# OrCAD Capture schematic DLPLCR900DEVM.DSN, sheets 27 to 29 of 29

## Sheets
27 P22-Slave Pwr/Gnd: size A3
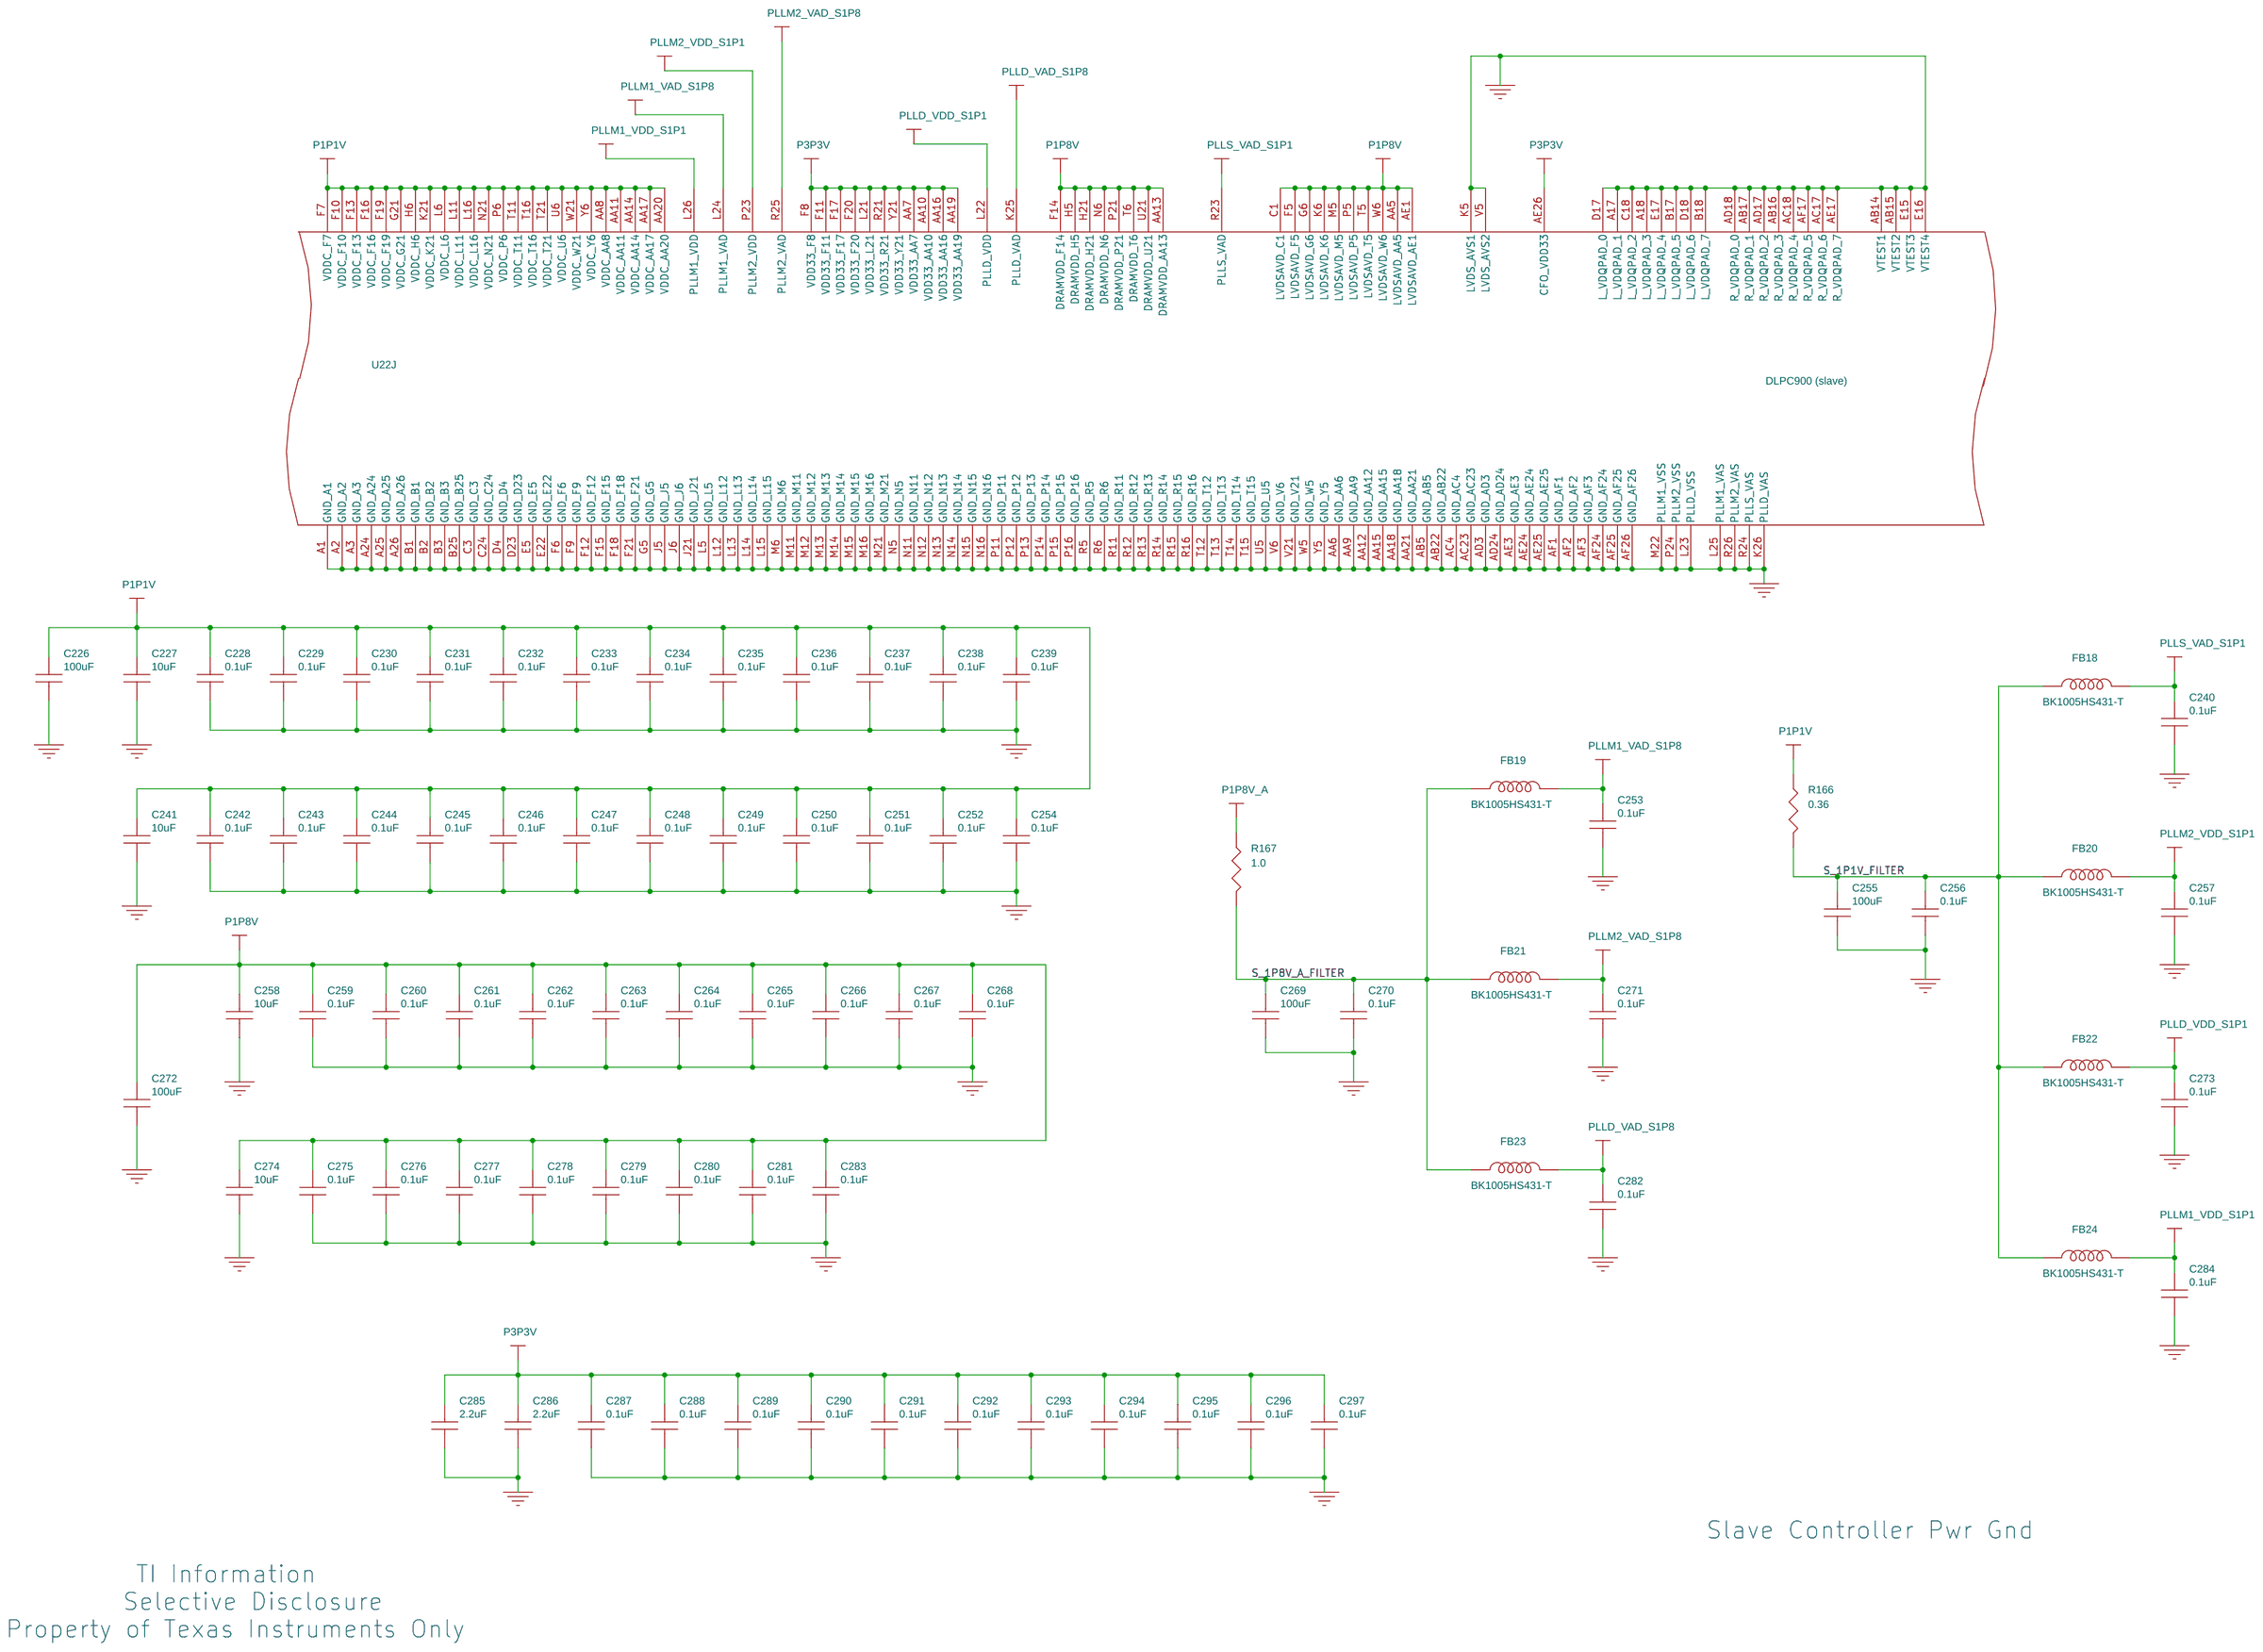
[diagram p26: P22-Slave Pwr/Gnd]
28 P17-Master Pwr/Gnd: size A3
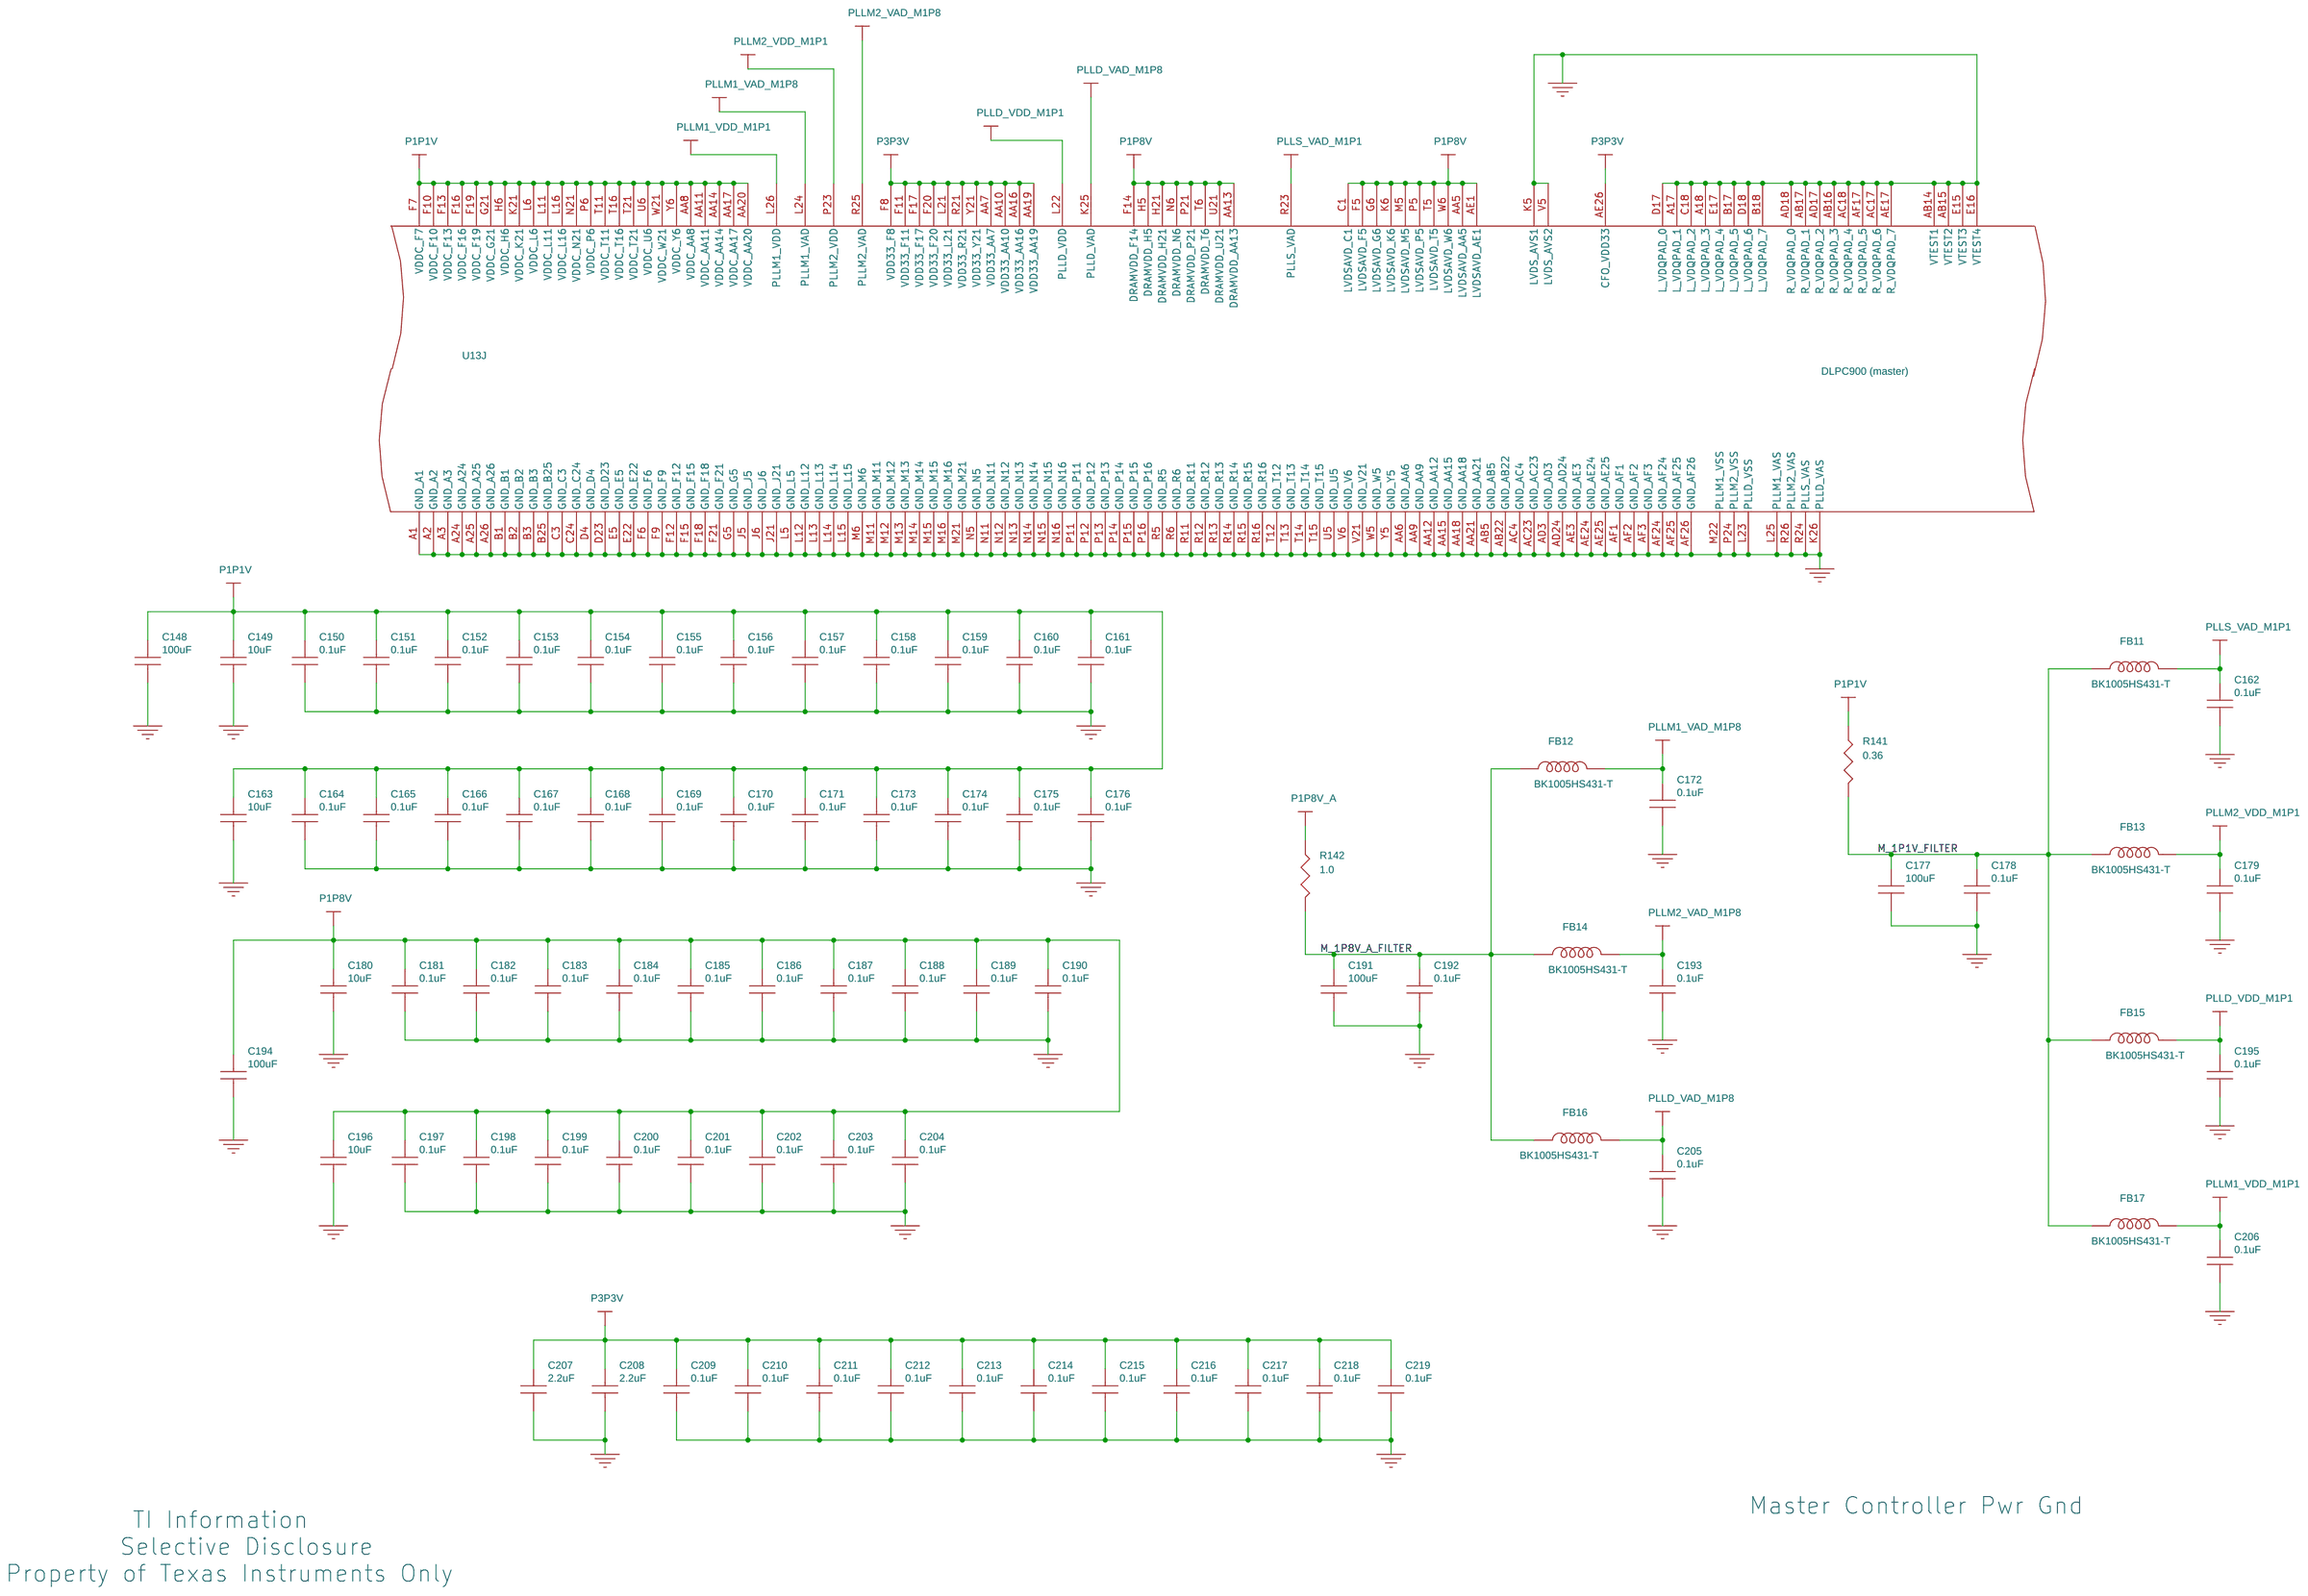
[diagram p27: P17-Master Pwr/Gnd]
29 P05-HDMI/DP Conn, ESD: size A3
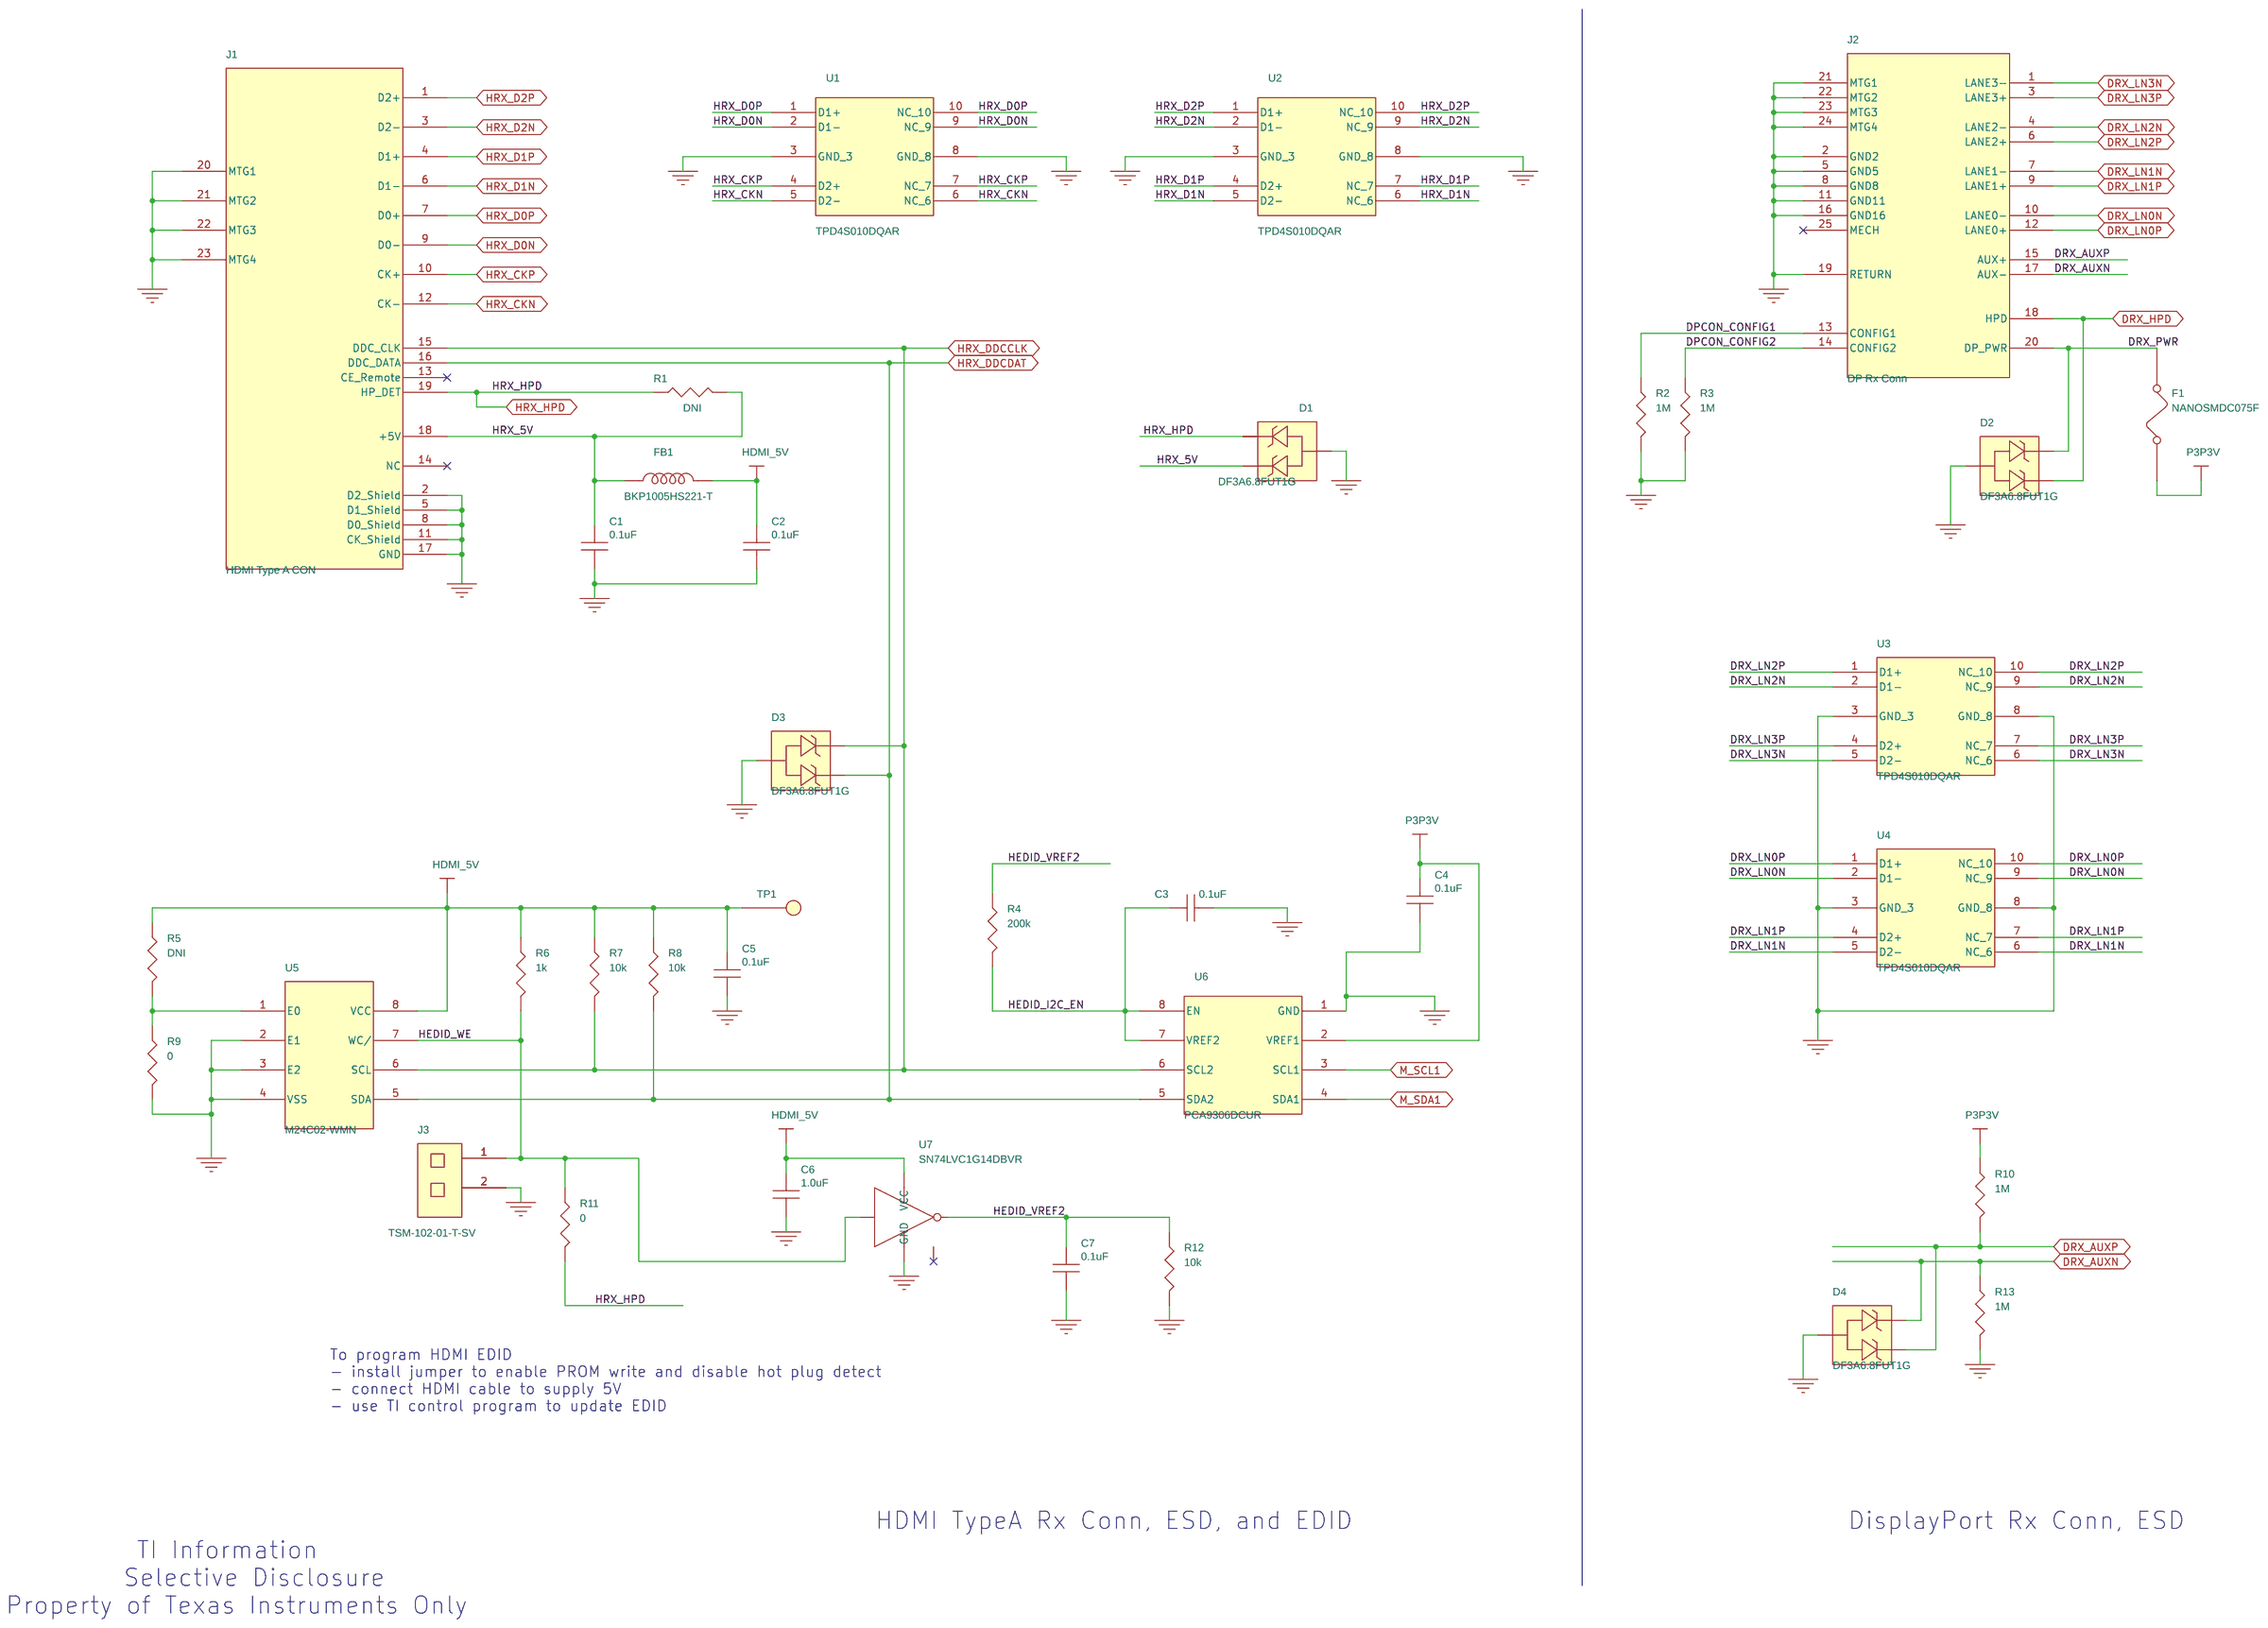
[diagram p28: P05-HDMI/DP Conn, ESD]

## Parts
sheet P05-HDMI/DP Conn, ESD
C1  0.1uF  [0402]
C2  0.1uF  [0402]
C3  0.1uF  [0402]
C4  0.1uF  [0402]
C5  0.1uF  [0402]
C6  1.0uF  [0402]
C7  0.1uF  [0402]
D1  DF3A6.8FUT1G  [SOT323]
D2  DF3A6.8FUT1G  [SOT323]
D3  DF3A6.8FUT1G  [SOT323]
D4  DF3A6.8FUT1G  [SOT323]
F1  NANOSMDC075F  [1206]
FB1  BKP1005HS221-T  [0402]
J1  HDMI Type A CON  [SMT]
J2  DP Rx Conn  [CONN20-47272-DISP_MOLEX]
J3  TSM-102-01-T-SV  [2POS-2p54mm]
R1  DNI  [0402]
R2  1M  [0402]
R3  1M  [0402]
R4  200k  [0402]
R5  DNI  [0402]
R6  1k  [0402]
R7  10k  [0402]
R8  10k  [0402]
R9  0  [0603]
R10  1M  [0402]
R11  0  [0402]
R12  10k  [0402]
R13  1M  [0402]
TP1  Testpoint  [24mil-plated]
U1  TPD4S010DQAR  [10-UFDFN]
U2  TPD4S010DQAR  [10-UFDFN]
U3  TPD4S010DQAR  [10-UFDFN]
U4  TPD4S010DQAR  [10-UFDFN]
U5  M24C02-WMN  [SO8]
U6  PCA9306DCUR  [8-VFSOP]
U7  SN74LVC1G14DBVR  [U_5_DBV]
sheet P14-Master Ext Flash Intf
U13  DLPC900 (master)  [516BGA]  (sections A,B,C,D,E,F,G,H,I,J)
sheet P17-Master Pwr/Gnd
C148  100uF  [1206]
C149  10uF  [0603]
C150  0.1uF  [0402]
C151  0.1uF  [0402]
C152  0.1uF  [0402]
C153  0.1uF  [0402]
C154  0.1uF  [0402]
C155  0.1uF  [0402]
C156  0.1uF  [0402]
C157  0.1uF  [0402]
C158  0.1uF  [0402]
C159  0.1uF  [0402]
C160  0.1uF  [0402]
C161  0.1uF  [0402]
C162  0.1uF  [0402]
C163  10uF  [0603]
C164  0.1uF  [0402]
C165  0.1uF  [0402]
C166  0.1uF  [0402]
C167  0.1uF  [0402]
C168  0.1uF  [0402]
C169  0.1uF  [0402]
C170  0.1uF  [0402]
C171  0.1uF  [0402]
C172  0.1uF  [0402]
C173  0.1uF  [0402]
C174  0.1uF  [0402]
C175  0.1uF  [0402]
C176  0.1uF  [0402]
C177  100uF  [1206]
C178  0.1uF  [0402]
C179  0.1uF  [0402]
C180  10uF  [0603]
C181  0.1uF  [0402]
C182  0.1uF  [0402]
C183  0.1uF  [0402]
C184  0.1uF  [0402]
C185  0.1uF  [0402]
C186  0.1uF  [0402]
C187  0.1uF  [0402]
C188  0.1uF  [0402]
C189  0.1uF  [0402]
C190  0.1uF  [0402]
C191  100uF  [1206]
C192  0.1uF  [0402]
C193  0.1uF  [0402]
C194  100uF  [1206]
C195  0.1uF  [0402]
C196  10uF  [0603]
C197  0.1uF  [0402]
C198  0.1uF  [0402]
C199  0.1uF  [0402]
C200  0.1uF  [0402]
C201  0.1uF  [0402]
C202  0.1uF  [0402]
C203  0.1uF  [0402]
C204  0.1uF  [0402]
C205  0.1uF  [0402]
C206  0.1uF  [0402]
C207  2.2uF  [0603]
C208  2.2uF  [0603]
C209  0.1uF  [0402]
C210  0.1uF  [0402]
C211  0.1uF  [0402]
C212  0.1uF  [0402]
C213  0.1uF  [0402]
C214  0.1uF  [0402]
C215  0.1uF  [0402]
C216  0.1uF  [0402]
C217  0.1uF  [0402]
C218  0.1uF  [0402]
C219  0.1uF  [0402]
FB11  BK1005HS431-T  [0402]
FB12  BK1005HS431-T  [0402]
FB13  BK1005HS431-T  [0402]
FB14  BK1005HS431-T  [0402]
FB15  BK1005HS431-T  [0402]
FB16  BK1005HS431-T  [0402]
FB17  BK1005HS431-T  [0402]
R141  0.36  [0402]
R142  1.0  [0402]
sheet P22-Slave Pwr/Gnd
C226  100uF  [1206]
C227  10uF  [0603]
C228  0.1uF  [0402]
C229  0.1uF  [0402]
C230  0.1uF  [0402]
C231  0.1uF  [0402]
C232  0.1uF  [0402]
C233  0.1uF  [0402]
C234  0.1uF  [0402]
C235  0.1uF  [0402]
C236  0.1uF  [0402]
C237  0.1uF  [0402]
C238  0.1uF  [0402]
C239  0.1uF  [0402]
C240  0.1uF  [0402]
C241  10uF  [0603]
C242  0.1uF  [0402]
C243  0.1uF  [0402]
C244  0.1uF  [0402]
C245  0.1uF  [0402]
C246  0.1uF  [0402]
C247  0.1uF  [0402]
C248  0.1uF  [0402]
C249  0.1uF  [0402]
C250  0.1uF  [0402]
C251  0.1uF  [0402]
C252  0.1uF  [0402]
C253  0.1uF  [0402]
C254  0.1uF  [0402]
C255  100uF  [1206]
C256  0.1uF  [0402]
C257  0.1uF  [0402]
C258  10uF  [0603]
C259  0.1uF  [0402]
C260  0.1uF  [0402]
C261  0.1uF  [0402]
C262  0.1uF  [0402]
C263  0.1uF  [0402]
C264  0.1uF  [0402]
C265  0.1uF  [0402]
C266  0.1uF  [0402]
C267  0.1uF  [0402]
C268  0.1uF  [0402]
C269  100uF  [1206]
C270  0.1uF  [0402]
C271  0.1uF  [0402]
C272  100uF  [1206]
C273  0.1uF  [0402]
C274  10uF  [0603]
C275  0.1uF  [0402]
C276  0.1uF  [0402]
C277  0.1uF  [0402]
C278  0.1uF  [0402]
C279  0.1uF  [0402]
C280  0.1uF  [0402]
C281  0.1uF  [0402]
C282  0.1uF  [0402]
C283  0.1uF  [0402]
C284  0.1uF  [0402]
C285  2.2uF  [0603]
C286  2.2uF  [0603]
C287  0.1uF  [0402]
C288  0.1uF  [0402]
C289  0.1uF  [0402]
C290  0.1uF  [0402]
C291  0.1uF  [0402]
C292  0.1uF  [0402]
C293  0.1uF  [0402]
C294  0.1uF  [0402]
C295  0.1uF  [0402]
C296  0.1uF  [0402]
C297  0.1uF  [0402]
FB18  BK1005HS431-T  [0402]
FB19  BK1005HS431-T  [0402]
FB20  BK1005HS431-T  [0402]
FB21  BK1005HS431-T  [0402]
FB22  BK1005HS431-T  [0402]
FB23  BK1005HS431-T  [0402]
FB24  BK1005HS431-T  [0402]
R166  0.36  [0402]
R167  1.0  [0402]
U22  DLPC900 (slave)  [516BGA]  (sections A,B,C,D,E,F,G,H,I,J)

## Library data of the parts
C1-C5 C7 = CER_0.1UF_25V_10%_X5R_0402
C6 = CER_1.0UF_16V_10%_X5R_0402: MFG: KEMET; MFG Part Number: C0402C105M4PAC7867
D1-D4 = TVS_ZENER_DUAL_SOT323
F1 = Fuse_Polyswitch.75A
FB1 = FERRITE_BEAD_220_OHM_800mA_0402
J1 = HDMI_Connector_0
J2 = DP_CONN_RCPT_R_A_W_O_FLANGE_0: MFG: Molex; MFG Part Number: 0472720001
J3 = TSM-102-01-T-SV_2POS_.1_SMD
R1 R5 R6 = 1.0K_OHM_1_16W_5%_0402
R2 R3 R10 R13 = 1M_OHM_1_10W_5%_0402
R4 = 200K_OHM_1_16W_5%_0402
R7 R8 R12 = 10K_OHM_1_10W_5%_0402
R9 = 0.0_OHM_1_10W_0603
R11 = 0.0_OHM_1_10W_0402
TP1 = Testpoint
U1-U4 = TPD4S010DQA
U5 = M24C08L_dsize
U6 = PCA9306DCUR
U7 = IC_SGL_SHMT-TRG_INV_SOT23-5
U13 U22 = DLPC900_910_datasheet
C148 C177 C191 C194 C226 C255 C269 C272 = CER_100UF_6.3V_20%_X5R_1206
C149 C163 C180 C196 C227 C241 C258 C274 = CER_10UF_10V_20%_X5R_0603
C150-C162 C164-C176 C178 C179 C181-C190 C192 C193 C195 C197-C206 C209-C219 C228-C240 C242-C254 C256 C257 C259-C268 C270 C271 C273 C275-C284 C287-C297 = CER_0.1UF_16V_10%_X5R_0402: MFG: Samsung; MFG Part Number: CL05A104KO5NNNC
C207 C208 C285 C286 = CER_2.2UF_25V_10%_X5R_0603
FB11-FB24 = FERRITE_BEAD_430OHM_0402
R141 R166 = 0.36_OHM_1_8W_1%_0402
R142 R167 = 1.00_OHM_1_16W_1%_0402

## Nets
GND: C1.2 C2.2 C3.2 C4.2 C5.2 C6.2 C7.2 C148.2 C149.2 C150.2 C151.2 C152.2 C153.2 C154.2 C155.2 C156.2 C157.2 C158.2 C159.2 C160.2 C161.2 C162.2 C163.2 C164.2 C165.2 C166.2 C167.2 C168.2 C169.2 C170.2 C171.2 C172.2 C173.2 C174.2 C175.2 C176.2 C177.2 C178.2 C179.2 C180.2 C181.2 C182.2 C183.2 C184.2 C185.2 C186.2 C187.2 C188.2 C189.2 C190.2 C191.2 C192.2 C193.2 C194.2 C195.2 C196.2 C197.2 C198.2 C199.2 C200.2 C201.2 C202.2 C203.2 C204.2 C205.2 C206.2 C207.2 C208.2 C209.2 C210.2 C211.2 C212.2 C213.2 C214.2 C215.2 C216.2 C217.2 C218.2 C219.2 C226.2 C227.2 C228.2 C229.2 C230.2 C231.2 C232.2 C233.2 C234.2 C235.2 C236.2 C237.2 C238.2 C239.2 C240.2 C241.2 C242.2 C243.2 C244.2 C245.2 C246.2 C247.2 C248.2 C249.2 C250.2 C251.2 C252.2 C253.2 C254.2 C255.2 C256.2 C257.2 C258.2 C259.2 C260.2 C261.2 C262.2 C263.2 C264.2 C265.2 C266.2 C267.2 C268.2 C269.2 C270.2 C271.2 C272.2 C273.2 C274.2 C275.2 C276.2 C277.2 C278.2 C279.2 C280.2 C281.2 C282.2 C283.2 C284.2 C285.2 C286.2 C287.2 C288.2 C289.2 C290.2 C291.2 C292.2 C293.2 C294.2 C295.2 C296.2 C297.2 D1.3 D2.3 D3.3 D4.3 J1.2(D2_Shield) J1.5(D1_Shield) J1.8(D0_Shield) J1.11(CK_Shield) J1.17(GND) J1.20(MTG1) J1.21(MTG2) J1.22(MTG3) J1.23(MTG4) J2.2(GND2) J2.5(GND5) J2.8(GND8) J2.11(GND11) J2.16(GND16) J2.19(RETURN) J2.21(MTG1) J2.22(MTG2) J2.23(MTG3) J2.24(MTG4) J3.2 R2.2 R3.2 R9.2 R12.2 R13.2 U1.3(GND) U1.8(GND) U2.3(GND) U2.8(GND) U3.3(GND) U3.8(GND) U4.3(GND) U4.8(GND) U5.2(E1) U5.3(E2) U5.4(VSS) U6.1(GND) U7.3(GND) U13.A1(GND) U13.A2(GND) U13.A3(GND) U13.A17(L_VDQPAD_1) U13.A18(L_VDQPAD_3) U13.A24(GND) U13.A25(GND) U13.A26(GND) U13.AA6(GND) U13.AA9(GND) U13.AA12(GND) U13.AA15(GND) U13.AA18(GND) U13.AA21(GND) U13.AB5(GND) U13.AB14(VTEST1) U13.AB15(VTEST2) U13.AB16(R_VDQPAD_3) U13.AB17(R_VDQPAD_1) U13.AB22(GND) U13.AC4(GND) U13.AC17(R_VDQPAD_6) U13.AC18(R_VDQPAD_4) U13.AC23(GND) U13.AD3(GND) U13.AD17(R_VDQPAD_2) U13.AD18(R_VDQPAD_0) U13.AD24(GND) U13.AE3(GND) U13.AE17(R_VDQPAD_7) U13.AE24(GND) U13.AE25(GND) U13.AF1(GND) U13.AF2(GND) U13.AF3(GND) U13.AF17(R_VDQPAD_5) U13.AF24(GND) U13.AF25(GND) U13.AF26(GND) U13.B1(GND) U13.B2(GND) U13.B3(GND) U13.B17(L_VDQPAD_5) U13.B18(L_VDQPAD_7) U13.B25(GND) U13.C3(GND) U13.C18(L_VDQPAD_2) U13.C24(GND) U13.D4(GND) U13.D17(L_VDQPAD_0) U13.D18(L_VDQPAD_6) U13.D23(GND) U13.E5(GND) U13.E15(VTEST3) U13.E16(VTEST4) U13.E17(L_VDQPAD_4) U13.E22(GND) U13.F6(GND) U13.F9(GND) U13.F12(GND) U13.F15(GND) U13.F18(GND) U13.F21(GND) U13.G5(GND) U13.J5(GND) U13.J6(GND) U13.J21(GND) U13.K5(LVDS_AVS1) U13.K26(PLLD_VAS) U13.L5(GND) U13.L12(GND) U13.L13(GND) U13.L14(GND) U13.L15(GND) U13.L23(PLLD_VSS) U13.L25(PLLM1_VAS) U13.M6(GND) U13.M11(GND) U13.M12(GND) U13.M13(GND) U13.M14(GND) U13.M15(GND) U13.M16(GND) U13.M21(GND) U13.M22(PLLM1_VSS) U13.N5(GND) U13.N11(GND) U13.N12(GND) U13.N13(GND) U13.N14(GND) U13.N15(GND) U13.N16(GND) U13.P11(GND) U13.P12(GND) U13.P13(GND) U13.P14(GND) U13.P15(GND) U13.P16(GND) U13.P24(PLLM2_VSS) U13.R5(GND) U13.R6(GND) U13.R11(GND) U13.R12(GND) U13.R13(GND) U13.R14(GND) U13.R15(GND) U13.R16(GND) U13.R24(PLLS_VAS) U13.R26(PLLM2_VAS) U13.T12(GND) U13.T13(GND) U13.T14(GND) U13.T15(GND) U13.U5(GND) U13.V5(LVDS_AVS2) U13.V6(GND) U13.V21(GND) U13.W5(GND) U13.Y5(GND) U22.A1(GND) U22.A2(GND) U22.A3(GND) U22.A17(L_VDQPAD_1) U22.A18(L_VDQPAD_3) U22.A24(GND) U22.A25(GND) U22.A26(GND) U22.AA6(GND) U22.AA9(GND) U22.AA12(GND) U22.AA15(GND) U22.AA18(GND) U22.AA21(GND) U22.AB5(GND) U22.AB14(VTEST1) U22.AB15(VTEST2) U22.AB16(R_VDQPAD_3) U22.AB17(R_VDQPAD_1) U22.AB22(GND) U22.AC4(GND) U22.AC17(R_VDQPAD_6) U22.AC18(R_VDQPAD_4) U22.AC23(GND) U22.AD3(GND) U22.AD17(R_VDQPAD_2) U22.AD18(R_VDQPAD_0) U22.AD24(GND) U22.AE3(GND) U22.AE17(R_VDQPAD_7) U22.AE24(GND) U22.AE25(GND) U22.AF1(GND) U22.AF2(GND) U22.AF3(GND) U22.AF17(R_VDQPAD_5) U22.AF24(GND) U22.AF25(GND) U22.AF26(GND) U22.B1(GND) U22.B2(GND) U22.B3(GND) U22.B17(L_VDQPAD_5) U22.B18(L_VDQPAD_7) U22.B25(GND) U22.C3(GND) U22.C18(L_VDQPAD_2) U22.C24(GND) U22.D4(GND) U22.D17(L_VDQPAD_0) U22.D18(L_VDQPAD_6) U22.D23(GND) U22.E5(GND) U22.E15(VTEST3) U22.E16(VTEST4) U22.E17(L_VDQPAD_4) U22.E22(GND) U22.F6(GND) U22.F9(GND) U22.F12(GND) U22.F15(GND) U22.F18(GND) U22.F21(GND) U22.G5(GND) U22.J5(GND) U22.J6(GND) U22.J21(GND) U22.K5(LVDS_AVS1) U22.K26(PLLD_VAS) U22.L5(GND) U22.L12(GND) U22.L13(GND) U22.L14(GND) U22.L15(GND) U22.L23(PLLD_VSS) U22.L25(PLLM1_VAS) U22.M6(GND) U22.M11(GND) U22.M12(GND) U22.M13(GND) U22.M14(GND) U22.M15(GND) U22.M16(GND) U22.M21(GND) U22.M22(PLLM1_VSS) U22.N5(GND) U22.N11(GND) U22.N12(GND) U22.N13(GND) U22.N14(GND) U22.N15(GND) U22.N16(GND) U22.P11(GND) U22.P12(GND) U22.P13(GND) U22.P14(GND) U22.P15(GND) U22.P16(GND) U22.P24(PLLM2_VSS) U22.R5(GND) U22.R6(GND) U22.R11(GND) U22.R12(GND) U22.R13(GND) U22.R14(GND) U22.R15(GND) U22.R16(GND) U22.R24(PLLS_VAS) U22.R26(PLLM2_VAS) U22.T12(GND) U22.T13(GND) U22.T14(GND) U22.T15(GND) U22.U5(GND) U22.V5(LVDS_AVS2) U22.V6(GND) U22.V21(GND) U22.W5(GND) U22.Y5(GND) ; also on sheet 1 3 4 5 7 8 9 10 11 13 14 15 16 17 18 19 23 25 26
DPCON_CONFIG1: J2.13(CONFIG1) R2.1
DPCON_CONFIG2: J2.14(CONFIG2) R3.1
DRX_AUXN: D4.2 J2.17(AUX-) R13.1 ; also on sheet 23
DRX_AUXP: D4.1 J2.15(AUX+) R10.2 ; also on sheet 23
DRX_HPD: D2.1 J2.18(HPD) ; also on sheet 23
DRX_LN0N: J2.10(LANE0-) U4.2(D1-) U4.9(NC) ; also on sheet 23
DRX_LN0P: J2.12(LANE0+) U4.1(D1+) U4.10(NC) ; also on sheet 23
DRX_LN1N: J2.7(LANE1-) U4.5(D2-) U4.6(NC) ; also on sheet 23
DRX_LN1P: J2.9(LANE1+) U4.4(D2+) U4.7(NC) ; also on sheet 23
DRX_LN2N: J2.4(LANE2-) U3.2(D1-) U3.9(NC) ; also on sheet 23
DRX_LN2P: J2.6(LANE2+) U3.1(D1+) U3.10(NC) ; also on sheet 23
DRX_LN3N: J2.1(LANE3-) U3.5(D2-) U3.6(NC) ; also on sheet 23
DRX_LN3P: J2.3(LANE3+) U3.4(D2+) U3.7(NC) ; also on sheet 23
DRX_PWR: D2.2 F1.2 J2.20(DP_PWR)
HDMI_5V: C2.1 C5.1 C6.1 FB1.2 R5.1 R6.1 R7.1 R8.1 TP1.1 U5.8(VCC) U7.5(VCC) ; also on sheet 23
HEDID_I2C_EN: C3.1 R4.2 U6.7(VREF2) U6.8(EN)
HEDID_VREF2: C7.1 R4.1 R12.1 U7.4
HEDID_WE: J3.1 R6.2 R11.1 U5.7(WC/) U7.2
HRX_5V: C1.1 D1.1 FB1.1 J1.18(+5V) R1.2
HRX_CKN: J1.12(CK-) U1.5(D2-) U1.6(NC) ; also on sheet 23
HRX_CKP: J1.10(CK+) U1.4(D2+) U1.7(NC) ; also on sheet 23
HRX_D0N: J1.9(D0-) U1.2(D1-) U1.9(NC) ; also on sheet 23
HRX_D0P: J1.7(D0+) U1.1(D1+) U1.10(NC) ; also on sheet 23
HRX_D1N: J1.6(D1-) U2.5(D2-) U2.6(NC) ; also on sheet 23
HRX_D1P: J1.4(D1+) U2.4(D2+) U2.7(NC) ; also on sheet 23
HRX_D2N: J1.3(D2-) U2.2(D1-) U2.9(NC) ; also on sheet 23
HRX_D2P: J1.1(D2+) U2.1(D1+) U2.10(NC) ; also on sheet 23
HRX_DDCCLK: D3.2 J1.15(DDC_CLK) R7.2 U5.6(SCL) U6.6(SCL2) ; also on sheet 23
HRX_DDCDAT: D3.1 J1.16(DDC_DATA) R8.2 U5.5(SDA) U6.5(SDA2) ; also on sheet 23
HRX_HPD: D1.2 J1.19(HP_DET) R1.1 R11.2 ; also on sheet 1
M_1P1V_FILTER: C177.1 C178.1 FB11.1 FB13.1 FB15.1 FB17.1 R141.2
M_1P8V_A_FILTER: C191.1 C192.1 FB12.1 FB14.1 FB16.1 R142.2
M_SCL1: U6.3(SCL1) ; also on sheet 1 10 15 23
M_SDA1: U6.4(SDA1) ; also on sheet 1 10 15 23
P1P1V: C148.1 C149.1 C150.1 C151.1 C152.1 C153.1 C154.1 C155.1 C156.1 C157.1 C158.1 C159.1 C160.1 C161.1 C163.1 C164.1 C165.1 C166.1 C167.1 C168.1 C169.1 C170.1 C171.1 C173.1 C174.1 C175.1 C176.1 C226.1 C227.1 C228.1 C229.1 C230.1 C231.1 C232.1 C233.1 C234.1 C235.1 C236.1 C237.1 C238.1 C239.1 C241.1 C242.1 C243.1 C244.1 C245.1 C246.1 C247.1 C248.1 C249.1 C250.1 C251.1 C252.1 C254.1 R141.1 R166.1 U13.AA8(VDDC) U13.AA11(VDDC) U13.AA14(VDDC) U13.AA17(VDDC) U13.AA20(VDDC) U13.F7(VDDC) U13.F10(VDDC) U13.F13(VDDC) U13.F16(VDDC) U13.F19(VDDC) U13.G21(VDDC) U13.H6(VDDC) U13.K21(VDDC) U13.L6(VDDC) U13.L11(VDDC) U13.L16(VDDC) U13.N21(VDDC) U13.P6(VDDC) U13.T11(VDDC) U13.T16(VDDC) U13.T21(VDDC) U13.U6(VDDC) U13.W21(VDDC) U13.Y6(VDDC) U22.AA8(VDDC) U22.AA11(VDDC) U22.AA14(VDDC) U22.AA17(VDDC) U22.AA20(VDDC) U22.F7(VDDC) U22.F10(VDDC) U22.F13(VDDC) U22.F16(VDDC) U22.F19(VDDC) U22.G21(VDDC) U22.H6(VDDC) U22.K21(VDDC) U22.L6(VDDC) U22.L11(VDDC) U22.L16(VDDC) U22.N21(VDDC) U22.P6(VDDC) U22.T11(VDDC) U22.T16(VDDC) U22.T21(VDDC) U22.U6(VDDC) U22.W21(VDDC) U22.Y6(VDDC) ; also on sheet 7 26
P1P8V: C180.1 C181.1 C182.1 C183.1 C184.1 C185.1 C186.1 C187.1 C188.1 C189.1 C190.1 C194.1 C196.1 C197.1 C198.1 C199.1 C200.1 C201.1 C202.1 C203.1 C204.1 C258.1 C259.1 C260.1 C261.1 C262.1 C263.1 C264.1 C265.1 C266.1 C267.1 C268.1 C272.1 C274.1 C275.1 C276.1 C277.1 C278.1 C279.1 C280.1 C281.1 C283.1 U13.AA5(LVDSAVD) U13.AA13(DRAMVDD) U13.AE1(LVDSAVD) U13.C1(LVDSAVD) U13.F5(LVDSAVD) U13.F14(DRAMVDD) U13.G6(LVDSAVD) U13.H5(DRAMVDD) U13.H21(DRAMVDD) U13.K6(LVDSAVD) U13.M5(LVDSAVD) U13.N6(DRAMVDD) U13.P5(LVDSAVD) U13.P21(DRAMVDD) U13.T5(LVDSAVD) U13.T6(DRAMVDD) U13.U21(DRAMVDD) U13.W6(LVDSAVD) U22.AA5(LVDSAVD) U22.AA13(DRAMVDD) U22.AE1(LVDSAVD) U22.C1(LVDSAVD) U22.F5(LVDSAVD) U22.F14(DRAMVDD) U22.G6(LVDSAVD) U22.H5(DRAMVDD) U22.H21(DRAMVDD) U22.K6(LVDSAVD) U22.M5(LVDSAVD) U22.N6(DRAMVDD) U22.P5(LVDSAVD) U22.P21(DRAMVDD) U22.T5(LVDSAVD) U22.T6(DRAMVDD) U22.U21(DRAMVDD) U22.W6(LVDSAVD) ; also on sheet 7 13 25
P1P8V_A: R142.1 R167.1 ; also on sheet 3
P3P3V: C4.1 C207.1 C208.1 C209.1 C210.1 C211.1 C212.1 C213.1 C214.1 C215.1 C216.1 C217.1 C218.1 C219.1 C285.1 C286.1 C287.1 C288.1 C289.1 C290.1 C291.1 C292.1 C293.1 C294.1 C295.1 C296.1 C297.1 F1.1 R10.1 U6.2(VREF1) U13.AA7(VDD33) U13.AA10(VDD33) U13.AA16(VDD33) U13.AA19(VDD33) U13.AE26(CFO_VDD33) U13.F8(VDD33) U13.F11(VDD33) U13.F17(VDD33) U13.F20(VDD33) U13.L21(VDD33) U13.R21(VDD33) U13.Y21(VDD33) U22.AA7(VDD33) U22.AA10(VDD33) U22.AA16(VDD33) U22.AA19(VDD33) U22.AE26(CFO_VDD33) U22.F8(VDD33) U22.F11(VDD33) U22.F17(VDD33) U22.F20(VDD33) U22.L21(VDD33) U22.R21(VDD33) U22.Y21(VDD33) ; also on sheet 3 4 7 8 9 10 11 12 13 14 15 16 17 18 19 23 25
PLLD_VAD_M1P8: C205.1 FB16.2 U13.K25(PLLD_VAD)
PLLD_VAD_S1P8: C282.1 FB23.2 U22.K25(PLLD_VAD)
PLLD_VDD_M1P1: C195.1 FB15.2 U13.L22(PLLD_VDD)
PLLD_VDD_S1P1: C273.1 FB22.2 U22.L22(PLLD_VDD)
PLLM1_VAD_M1P8: C172.1 FB12.2 U13.L24(PLLM1_VAD)
PLLM1_VAD_S1P8: C253.1 FB19.2 U22.L24(PLLM1_VAD)
PLLM1_VDD_M1P1: C206.1 FB17.2 U13.L26(PLLM1_VDD)
PLLM1_VDD_S1P1: C284.1 FB24.2 U22.L26(PLLM1_VDD)
PLLM2_VAD_M1P8: C193.1 FB14.2 U13.R25(PLLM2_VAD)
PLLM2_VAD_S1P8: C271.1 FB21.2 U22.R25(PLLM2_VAD)
PLLM2_VDD_M1P1: C179.1 FB13.2 U13.P23(PLLM2_VDD)
PLLM2_VDD_S1P1: C257.1 FB20.2 U22.P23(PLLM2_VDD)
PLLS_VAD_M1P1: C162.1 FB11.2 U13.R23(PLLS_VAD)
PLLS_VAD_S1P1: C240.1 FB18.2 U22.R23(PLLS_VAD)
S_1P1V_FILTER: C255.1 C256.1 FB18.1 FB20.1 FB22.1 FB24.1 R166.2
S_1P8V_A_FILTER: C269.1 C270.1 FB19.1 FB21.1 FB23.1 R167.2
N20158334: R5.2 R9.1 U5.1(E0)

Not connected (* = marked no-connect by the designer): J1 13(CE_Remote)* 14(NC)*; J2 25(MECH)*; U7 1*

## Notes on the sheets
sheet 27
- Slave Controller Pwr Gnd
- TI Information
           Selective Disclosure
  Property of Texas Instruments Only
sheet 28
- Master Controller Pwr Gnd
- TI Information
           Selective Disclosure
  Property of Texas Instruments Only
sheet 29
- To program HDMI EDID
  - install jumper to enable PROM write and disable hot plug detect
  - connect HDMI cable to supply 5V
  - use TI control program to update EDID
- HDMI TypeA Rx Conn, ESD, and EDID
- DisplayPort Rx Conn, ESD
- TI Information
           Selective Disclosure
  Property of Texas Instruments Only
